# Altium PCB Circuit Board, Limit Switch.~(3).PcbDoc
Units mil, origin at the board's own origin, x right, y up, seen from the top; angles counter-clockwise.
Board outline 1122.99 x 1124 mil, 2 copper layers (Top Layer, Bottom Layer); 0 components, 2 nets, 8 pads, 0 vias.
Unrouted connection lines stored in the file: 1.
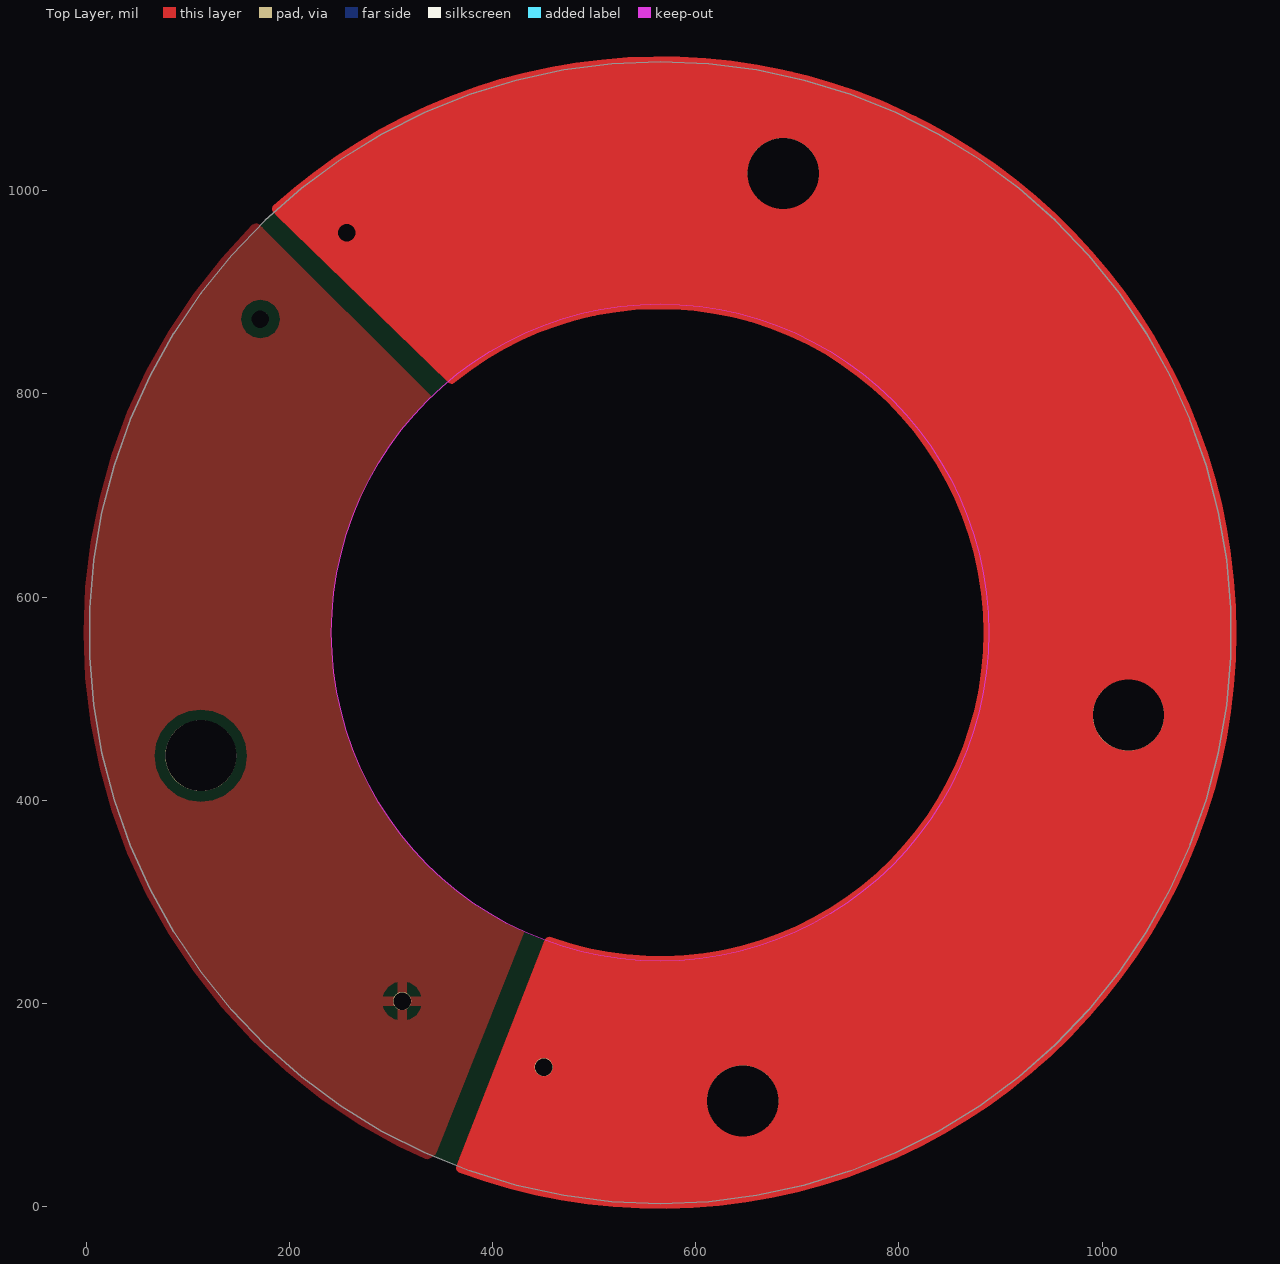
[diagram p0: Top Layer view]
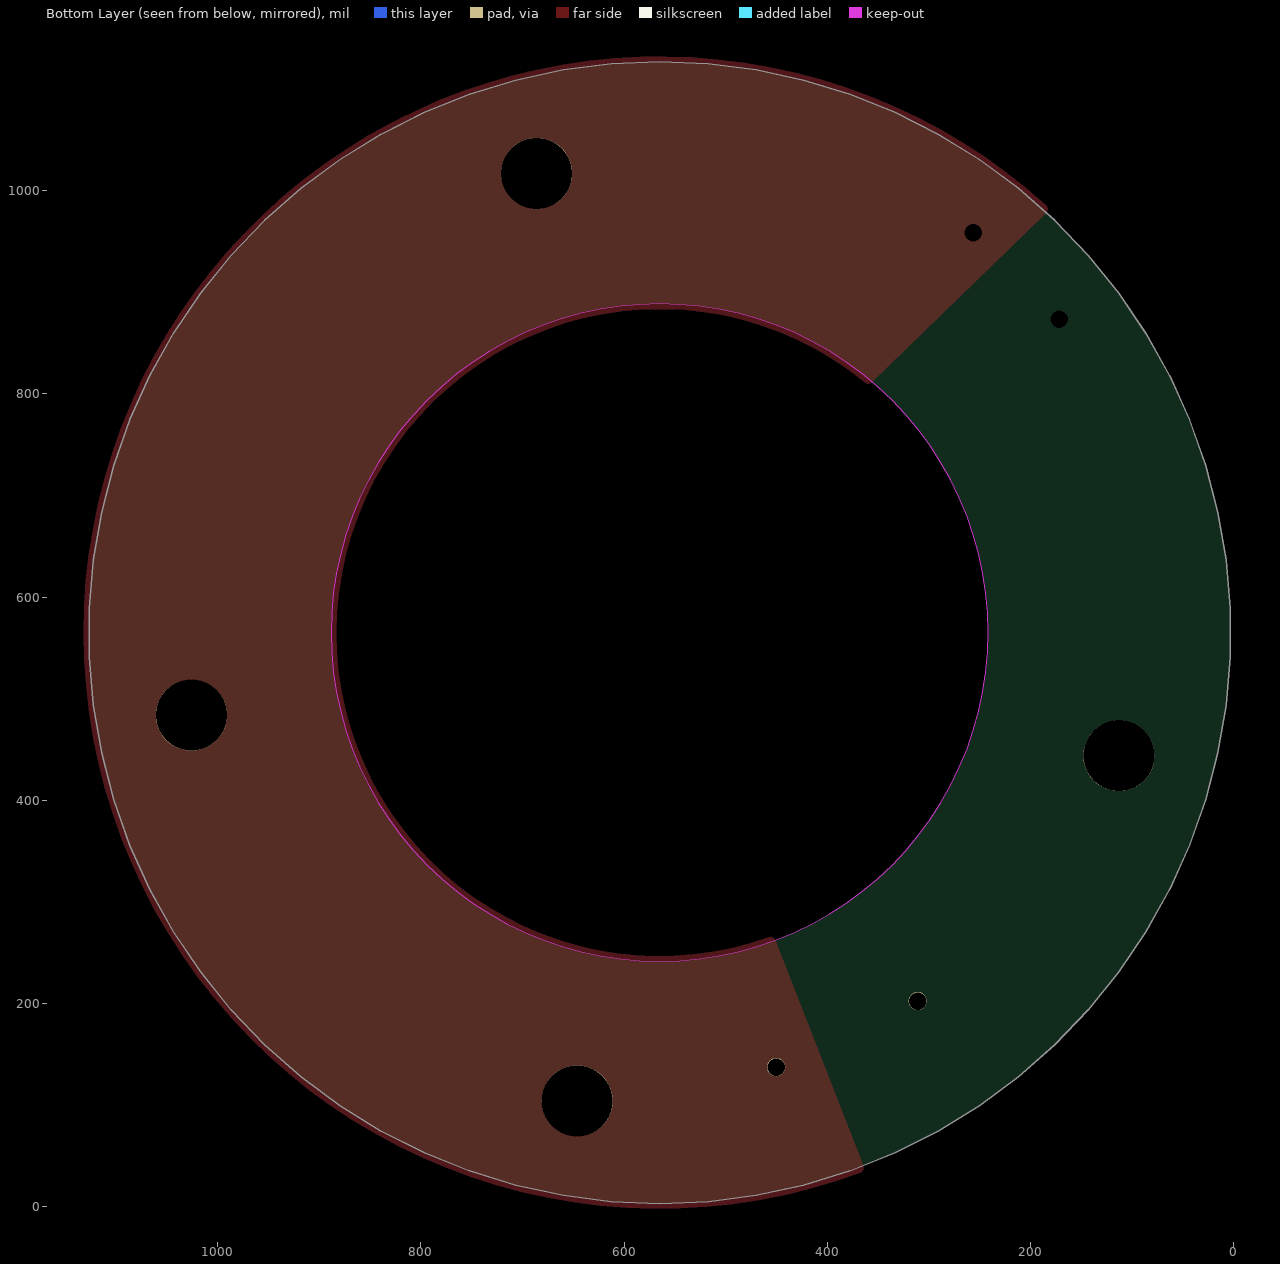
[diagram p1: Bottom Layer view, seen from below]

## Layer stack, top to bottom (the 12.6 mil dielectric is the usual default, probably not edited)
Top Layer: signal copper 1.4
Dielectric: dielectric 12.6, FR-4, Dk 4.8
Bottom Layer: signal copper 1.4

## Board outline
565,1127 517.34,1124.98 470.02,1118.92 423.39,1108.87 377.78,1094.9 333.51,1077.11 290.92,1055.63 250.29,1030.62 211.94,1002.26 176.13,970.74 143.12,936.3 113.15,899.18 86.44,859.66 63.18,818.01 43.53,774.55 27.63,729.57 15.61,683.4 7.55,636.38 3.51,588.85 3.51,541.15 7.55,493.62 15.61,446.6 27.63,400.43 43.53,355.45 63.18,311.99 86.44,270.34 113.15,230.82 143.12,193.7 176.13,159.26 211.94,127.74 250.29,99.38 290.92,74.37 333.51,52.89 377.78,35.1 423.39,21.13 470.02,11.08 517.34,5.02 565,3 612.66,5.02 659.98,11.08 706.61,21.13 752.22,35.1 796.49,52.89 839.08,74.37 879.71,99.38 918.06,127.74 953.87,159.26 986.88,193.7 1016.85,230.82 1043.56,270.34 1066.82,311.99 1086.47,355.45 1102.37,400.43 1114.39,446.6 1122.45,493.62 1126.49,541.15 1126.49,588.85 1122.45,636.38 1114.39,683.4 1102.37,729.57 1086.47,774.55 1066.82,818.01 1043.56,859.66 1016.85,899.18 986.88,936.3 953.87,970.74 918.06,1002.26 879.71,1030.62 839.08,1055.63 796.49,1077.11 752.22,1094.9 706.61,1108.87 659.98,1118.92 612.66,1124.98
cut-out: 565,241.5 cw(c565,565) 241.5,565 cw(c565,565) 565,888.5 cw(c565,565) 888.5,565 cw(c565,565)

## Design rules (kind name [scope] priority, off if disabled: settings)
Clearance [All] p1: gap=10
PolygonConnect [All] p1: connectstyle=Relief reliefconductorwidth=10 reliefentries=4 polygonreliefangle="90 Angle"
RoutingVias [All] p1: holewidth=28 width=50 viastyle="Through Hole" minholewidth=28 minwidth=50 maxholewidth=28 maxwidth=50
SilkscreenOverComponentPads [All] p1: minsilkscreentomaskgap=10
SolderMaskExpansion [All] p1: expansion=4
Width [All] p1: maxlimit=10 minlimit=10 preferedwidth=10
27 further rules are at their usual default settings.

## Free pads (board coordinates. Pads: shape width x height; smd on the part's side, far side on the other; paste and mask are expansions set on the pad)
  round 70 hole 70 unplated: 1(112.95,443.87)
  round 16.1 hole 17.1: 1(171.57,873.57) 1(256.43,958.42)
  round 18 hole 17.1: 1(311.05,202.32) 1(450.41,137.34)
  round 70 hole 70: 1(646.27,104.11) 1(686.13,1017.05) 1(1025.89,483.73)

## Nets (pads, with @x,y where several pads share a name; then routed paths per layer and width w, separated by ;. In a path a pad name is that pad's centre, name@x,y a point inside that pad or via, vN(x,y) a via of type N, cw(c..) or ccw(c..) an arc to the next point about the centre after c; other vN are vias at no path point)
SW1: pad.1@171.57,873.57 pad.1@311.05,202.32
SW2: pad.1@256.43,958.42 pad.1@450.41,137.34
copper on no net: | length 4766.8
  Top Layer w10: 170,875.15 171.57,873.57 ; 188.21,981.98 cw(c565,565) 369.32,38.17 ; 195,985 364.45,820.44 ; 300.43,5842.16 ccw(c565,5656) 426.69,5363.56 ; 359.77,815.07 cw(c565,565) 456.02,260.41 370,40

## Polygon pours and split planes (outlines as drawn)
SW1 on Top Layer "Top Layer-SW1" (solid, pour order 2): 333.78,47.27 cw(c565,565) 164.06,965.94 cw(c167.61,962.39) 172.14,964.53 cw(c170,960) 173.55,963.55 339.52,797.57 cw(c335.98,794.02) 339.66,797.43 cw(c336.25,793.75) 341.27,793.75 cw(c336.25,793.75) 339.8,790.2 ccw(c565,565) 428.8,277.11 ccw(c565,565) 428.83,277.09 cw(c426.69,272.56) 431.7,272.56 cw(c426.69,272.56) 431.28,270.55 344.66,53.14 cw(c340,55) 340.49,50.01 cw(c335.82,51.85)

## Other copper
Top Layer:
  region net SW2: 365.05,40.8 ccw(c369.32,38.17) 367.57,33.47 ccw(c565,565) 1132.02,565 ccw(c565,565) 184.85,985.7 ccw(c188.21,981.98) 185.52,977.75 ccw(c190,980) 186.51,976.4 355.84,811.96 ccw(c359.77,815.07) 362.96,811.19 cw(c565,565) 883.49,565 cw(c565,565) 457.75,265.12 cw(c565,565) 457.71,265.13 457.75,265.12 ccw(c456.02,260.41) 451.34,262.23 451.35,262.24 ccw(c456.02,260.41) 451.34,262.23 365.33,41.82 ccw(c370,40)

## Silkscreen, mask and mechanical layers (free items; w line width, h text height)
Mechanical 1:
  circle w10: c565,565 r562
  circle w10: c565,565 r323.5
  lines w10: 167.61,962.39 ccw(c565,565) 335.82,51.85 ; 170,960 335.98,794.02 ; 336.25,793.75 ccw(c565,565) 426.69,272.56 340,55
